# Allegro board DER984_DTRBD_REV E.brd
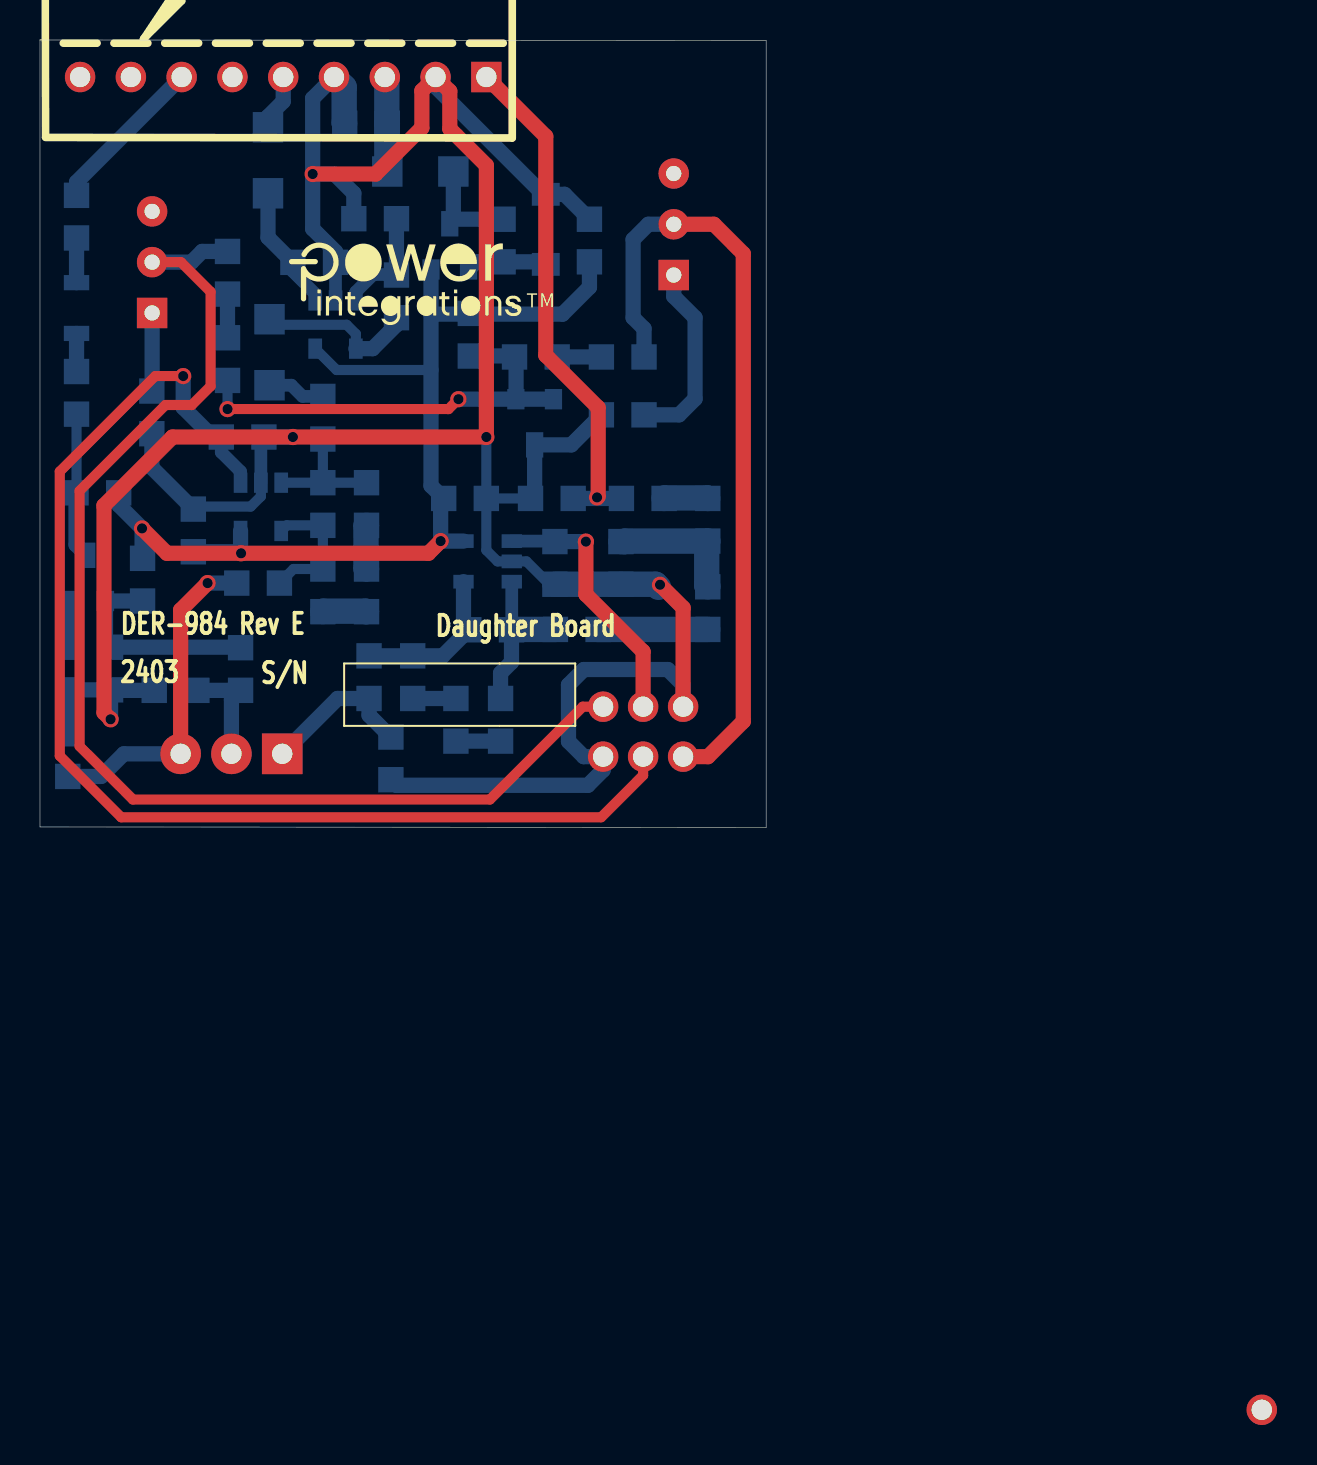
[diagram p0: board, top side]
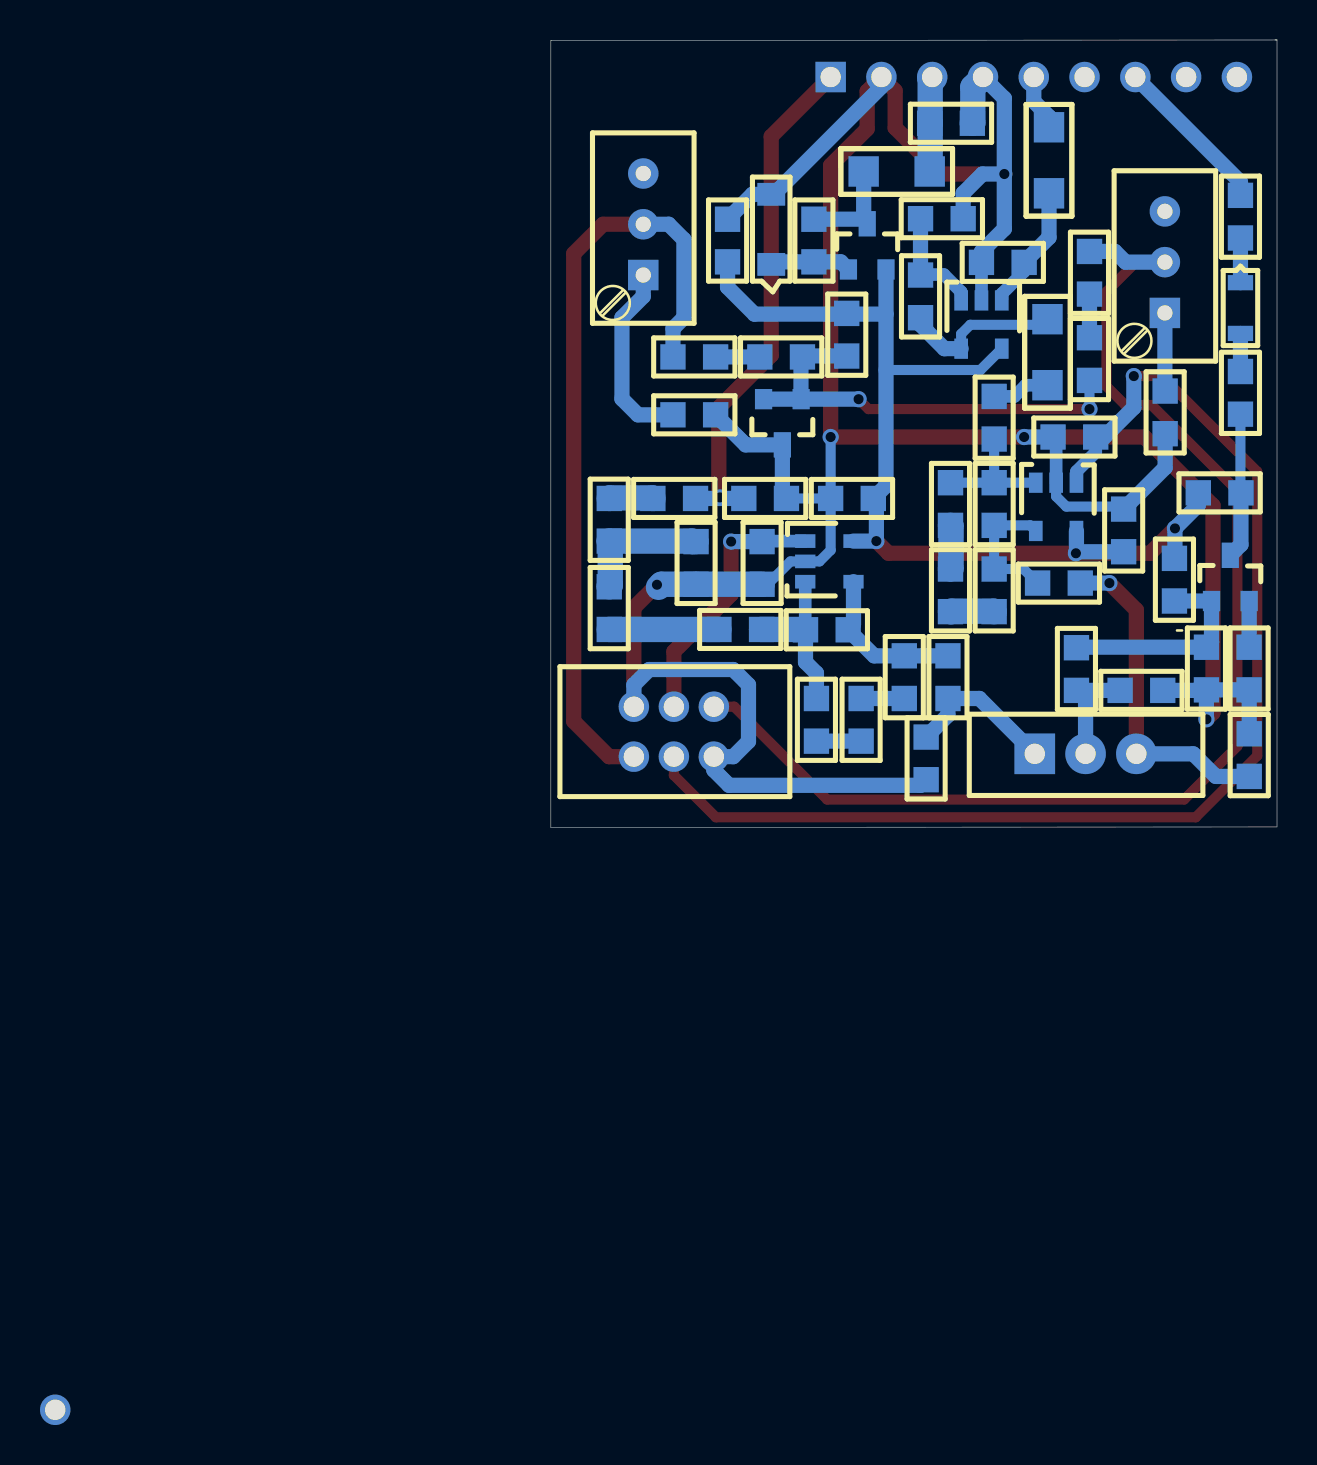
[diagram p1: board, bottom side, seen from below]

Outline 36.32 x 39.4 mm; copper layers: TOP, BOTTOM. Coordinates in mm from the lower left corner of the outline.
Outline path: 0,39.4 0,0.03 36.32,0 36.32,39.37 0,39.4 ; 0,39.4 0.1,39.4 0,39.4

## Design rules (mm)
constraint set DEFAULT: min track width 0.508

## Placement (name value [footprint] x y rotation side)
C1  10 nF  [PISMC0805]  12.65 28.27 0 bottom
C2  100 pf  [PISMC0805]  26.67 16.46 180 bottom
C3  10 uF  [PISMC0805]  17.37 35.23 180 bottom
C7  10 uF  [PISMC0805]  27.48 28.3 90 bottom
C8  10 nF  [PISMC0805]  14.15 10.79 90 bottom
C9  10 nF  [PISMC0805]  18.64 6.45 90 bottom
C10  10 uF  [PISMC0805]  20.19 16.46 0 bottom
C11  10 uF  [PISMC0805]  7.67 13.79 90 bottom
C13  470 nF  [PISMC0805]  14.15 17.25 270 bottom
C14  470 nF  [PISMC0805]  23.58 9.89 180 bottom
D1  BAV16WS-7-F  [PISMSOD323]  1.83 27.25 270 bottom
J9  CON10  [PI_UNSHROUD_10RA]  22.33 37.54 180 top
NOREF  -  []  12.47 29.69 0 top
NOREF#2  -  []  0 0.03 90 top
NOREF#3  -  []  -230.38 -156.18 0 top
NOREF#4  -  []  0 0.03 0 top
NOREF#5  -  []  -152.56 42.83 0 top
Q1  MMBT2222ALT1G  [PISMSOT23123_1]  19.56 27.91 180 bottom
Q2  MMBT2222ALT1G  [PISMSOT23123_1]  1.4 11.33 180 bottom
R1  5.11 k  [PISMR1206]  11.4 31.72 90 bottom
R2  1.00 k  [PISMR0805]  15.7 30.45 0 bottom
R3  0 R  [PISMR1206]  11.48 25.43 270 bottom
R5  0.0  [PISMR0805]  29.08 16.46 0 bottom
R6  2 k  [PISMR0805]  14.15 19.43 90 bottom
R7  9.09 k  [PISMR0805]  17.83 25.5 90 bottom
R8  100 k  [PISMR0805]  33.4 14.33 90 bottom
R9  1.02 k  [PISMR0805]  29.06 12.17 90 bottom
R10  20  [PISMR1206]  17.37 32.82 0 bottom
R11  1 k  [PISMR0805]  23.16 28.3 90 bottom
R13  2 k  [PISMR0805]  33.4 9.91 90 bottom
R17  100 k  [PISMR0805]  11.2 19.53 180 bottom
R18  0.0  [PISMR0805]  27.91 9.91 180 bottom
R19  43 K  [PISMR0805]  16.33 15.11 90 bottom
R20  100 k  [PISMR0805]  25.76 12.17 90 bottom
R21  43 K  [PISMR0805]  23.04 4.32 90 bottom
R22  43 K  [PISMR0805]  16.33 10.79 90 bottom
R23  43 K  [PISMR0805]  20.8 6.45 270 bottom
R25  2.2 k  [PISMR0805]  16.46 6.45 90 bottom
R26  2.2 k  [PISMR0805]  10.03 6.86 90 bottom
R28  14.7 k  [PISMR0805]  5.13 13.46 270 bottom
R29  13.7 k  [PISMR0805]  3.53 9.02 270 bottom
R31  1.00 k  [PISMR0805]  1.8 16.74 0 bottom
R32  300  [PISMR0805]  1.4 9.02 270 bottom
R34  1.00 k  [PISMR0805]  1.83 20.68 90 bottom
R39  0.0  [PISMR0805]  1.83 29.49 90 bottom
R40  1 k  [PISMR0805]  21.52 23.58 90 bottom
R41  316  [PISMR0805]  23.74 23.54 0 bottom
R42  9.1 k  [PISMR0805]  28.08 23.54 0 bottom
R43  5 k  [PIVRESPV36W_MURATA_1]  31.7 27.64 90 bottom
R44  0.0  [PISMR0805]  28.08 20.64 0 bottom
R46  316  [PISMR0805]  9.38 22.36 90 bottom
R47  9.1 k  [PISMR0805]  9.38 26.68 90 bottom
R48  5 k  [PIVRESPV36W_MURATA_1]  5.61 25.74 90 bottom
R49  0.0  [PISMR0805]  5.6 19.7 90 bottom
R50  2.2 k  [PISMR0805]  1.39 4.69 270 bottom
R51  2.2 k  [PISMR0805]  11.98 12.23 180 bottom
R52  2.2 k  [PISMR0805]  17.55 2.39 90 bottom
R53  2.2 k  [PISMR0805]  5.71 6.86 0 bottom
SW1  SPDT SLIDE  [PI_SWITCH_SPDT_SLIDE_PCBM_1]  12.12 3.68 270 bottom
SW2  DPDT SLIDE  [PI_SWITCH_DPDT_SLIDE_EG2209]  28.17 3.54 0 bottom
U1  LM321  [PISMSOT235]  13.77 26.37 0 bottom
U3  LM321  [PISMSOT235]  23.6 14.33 270 bottom
U4  LM321  [PISMSOT235]  10.03 17.25 0 bottom
U6  TL431CDBZR  [PISMSOT23123_1]  25.68 21.42 0 bottom
VR1  MMSZ5234B-TP  [PI_SM_SOD-123_12]  25.3 28.17 90 bottom

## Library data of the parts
C1 C8-C11 = CAP NP: room: 2
C2 C7 C13 C14 = CAP NP
C3 = CAP NP: alternate symbols: (pismc0805_1)
D1 = DIODE
J9 = CON10
Q1 Q2 = NPN_BEC
R1-R3 R6-R11 R13 R17 R19-R23 R25 R26 R28 R29 R31 R32 R34 R40-R42 R46 R47 R50-R53 = R
R5 R18 R39 R44 R49 = R: alternate symbols: (pismr0805_1)
R43 R48 = POT
SW1 = SW SLIDE-SPDT
SW2 = SW SLIDE-DPDT
U1 U4 = LM321_SOT23-5: room: 2
U3 = LM321_SOT23-5
U6 = TL431CDBZR
VR1 = DIODE_ZENER

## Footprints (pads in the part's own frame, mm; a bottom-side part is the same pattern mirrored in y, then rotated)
PI_SM_SOD-123_12
  rect 1.143x1.397 smd: 1(0,0) 2(3.505,0)
PI_SWITCH_DPDT_SLIDE_EG2209
  round 1.524 hole 1.016: 1(0,0) 2(1.999,0) 3(4,0) 4(0,-2.499) 5(1.999,-2.499) 6(4,-2.499)
PI_SWITCH_SPDT_SLIDE_PCBM_1
  rect 2.032x2.032 hole 1.016: 1(0,0)
  round 2.032 hole 1.016: 2(0,2.54) 3(0,5.08)
PI_UNSHROUD_10RA
  rect 1.524x1.524 hole 1.016: 1(0,0)
  round 1.524 hole 1.016: 2(2.54,0) 3(5.08,0) 4(7.62,0) 5(10.16,0) 6(12.7,0) 7(15.24,0) 8(17.78,0) 9(20.32,0) 10(-38.786,66.675)
PISMC0805
  rect 1.27x1.27 smd: 1(0,0) 2(2.134,0)
PISMR0805
  rect 1.27x1.27 smd: 1(0,0) 2(2.134,0)
PISMR1206
  rect 1.524x1.524 smd: 1(0,0) 2(3.302,0)
PISMSOD323
  rect 0.762x1.27 smd: 1(0,0) 2(2.54,0)
PISMSOT235
  rect 0.686x1.016 smd: 1(0,0) 2(1.016,0) 3(2.032,0) 4(2.032,2.413) 5(0,2.413)
PISMSOT23123_1
  rect 0.864x1.016 smd: 1(-1.88,0) 2(0,0)
  rect 0.864x1.27 smd: 3(-0.94,2.286)
PIVRESPV36W_MURATA_1
  rect 1.524x1.524 hole 0.762: 1(0,0)
  round 1.524 hole 0.762: 2(2.54,0) 3(5.08,0)

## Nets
+2.5V_REF: R40.1 R41.1 R46.1 U6.1 U6.2(VREF)
+5V_REF: C7.1 C10.1 C11.1 Q1.2(EMITTER) R28.1 R31.2 R40.2 U1.5 U3.5 U4.5
BPS: C3.1 J9.3 R10.1
CC_COMP: J9.6
CC_FB: J9.7 R39.2
GSA: C1.2 C2.2 C3.2 C7.2 C10.2 C11.2 J9.2 J9.4 R2.1 R9.1 R17.1 R20.1 R29.2 R32.2 R44.1 R49.1 R50.1 R52.1 R53.1 SW2.1 SW2.6 U1.2(V-) U3.2(V-) U4.2(V-) U6.3 VR1.2
HV: C2.1 J9.1 R5.1
ISENSE: J9.5 R1.2
REF_GEN_CC: R42.2 R43.2(WIPER) SW2.3
REF_GEN_CV: R47.2 R48.2(WIPER) SW2.4
REFCC: R17.2 SW2.2 U4.1
REFCV: R20.2 SW2.5 U3.1
N00379: Q1.1 R11.1 VR1.1
N00417: Q1.3 R10.2 R11.2
N01749: C14.1 R18.2 R21.2 U3.3
N01999: C9.2 C14.2 R25.2 U3.4
N02394: R8.1 R9.2 R13.2
N05104: D1.2 R34.2
N05139: D1.1 R39.1
N05314: Q2.1 R26.2 R28.2 R29.1
N05328: Q2.2(EMITTER) R32.1
N05332: Q2.3 R31.1 R34.1
N05564: R26.1 R53.2 SW1.2
N12614042: C8.2 C13.2 R51.1 U4.4
N12614046: C8.1 R22.1
N12615868: C13.1 R6.1 R19.2 U4.3
N12617691: R25.1 R52.2 SW1.1
N12617727: R50.2 R51.2 SW1.3
N12619254: R13.1 R18.1
N12620095: R21.1 R23.2
N12620099: C9.1 R23.1
N12620908: R19.1 R22.2
N12623730: C1.1 R1.1 U1.1
N12624245: R2.2 R7.2 U1.3
N12624261: R3.1 R7.1 U1.4
N12625090: R3.2 R6.2
N12627076: R5.2 R8.2
N12646098: R41.2 R42.1
N12647952: R43.1 R44.2
N12648329: R46.2 R47.1
N12648469: R48.1 R49.2

Pads without a net: J9 8 9 10; R43 3; R48 3

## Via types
v1: diameter 0.813, hole 0.508, TOP to BOTTOM, 14 vias

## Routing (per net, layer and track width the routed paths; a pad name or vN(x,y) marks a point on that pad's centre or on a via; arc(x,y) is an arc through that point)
+2.5V_REF: length 22.3
  TOP w0.508: v1(20.93,21.42) 20.43,20.93 v1(9.38,20.93)
  BOTTOM w0.508: v1(9.38,20.93) R46.1
  BOTTOM w0.762: U6.1 U6.2 ; U6.1 23.8,21.63 23.81,21.64 23.81,23.46 R41.1 23.69,23.59 21.53,23.59 R40.1 ; U6.1 v1(20.93,21.42)
+5V_REF: length 54
  TOP w0.762: v1(5.11,14.96) 6.35,13.72 v1(10.06,13.72) 19.43,13.72 v1(20.04,14.33)
  BOTTOM w0.508: 19.56,22.89 14.83,22.89 U1.5
  BOTTOM w0.762: C7.1 27.48,27.03 26.14,25.68 21.51,25.68 ; 19.56,25.68 19.56,17.09 C10.1 20.04,16.31 v1(20.04,14.33) U3.5 ; 19.56,25.68 21.51,25.68 ; 19.56,25.68 Q1.2 ; 21.51,25.68 21.52,25.69 R40.2 ; R31.2 3.94,16.13 v1(5.11,14.96) 5.11,13.49 R28.1 ; 10.03,13.79 U4.5 ; 10.03,13.79 C11.1 ; 10.03,13.79 10.06,13.77 v1(10.06,13.72)
BPS: length 4.8
  BOTTOM w1.27: J9.3 17.35,37.44 17.35,35.26 C3.1 17.35,35.2 17.35,32.84 R10.1
CC_FB: length 8.1
  BOTTOM w0.762: J9.7 1.83,32.28 R39.2
GSA: length 164.6
  TOP w0.762: SW2.6 32.17,10.99 v1(31.01,12.14) ; v1(13.64,32.69) 16.79,32.69 19.1,35 19.1,36.86 J9.2 20.5,36.83 20.5,34.95 22.33,33.12 v1(22.33,19.53) v1(12.65,19.53) 6.63,19.53 3.2,16.1 3.2,5.74 v1(3.53,5.41)
  BOTTOM w0.508: C11.2 7.8,16.05 10.54,16.05 11.05,16.56 U4.2 ; C10.2 v1(22.33,19.53) ; C10.2 22.33,13.87 22.89,13.31 U3.2 24.33,13.31 25.48,12.17 R20.1 ; C10.2 C2.2
  BOTTOM w0.635: C1.2 U1.2 ; R17.1 11.05,19.38 U4.2
  BOTTOM w0.762: C11.2 5.6,18 R49.1 ; v1(13.64,32.69) 13.64,36.47 J9.4 ; v1(13.64,32.69) 13.64,29.95 14.78,28.8 C1.2 ; v1(13.64,32.69) 14.73,32.69 15.7,31.72 R2.1 ; R53.1 3.56,6.86 R29.2 ; R50.1 1.39,6.88 1.4,6.88 R29.2 ; C7.2 26.24,31.67 VR1.2 25.17,31.67 19.79,37.06 J9.2 ; v1(12.65,19.53) R17.1 ; 30.78,12.17 30.91,12.17 30.94,12.14 v1(31.01,12.14) ; R52.1 17.83,2.11 27.41,2.11 28.17,2.87 SW2.1 27.2,3.54 26.44,4.3 26.44,7.13 27.2,7.9 31.4,7.9 32.17,7.13 SW2.6 ; R44.1 26.58,19.14 U6.3 24.74,16.66 C2.2 ; R29.2 v1(3.53,5.41)
  BOTTOM w1.27: J9.4 15.21,37.03 15.21,35.26 C3.2 ; R20.1 R9.1 30.78,12.17 30.94,12.01
HV: length 25.9
  TOP w0.762: v1(27.86,16.51) 27.92,16.57 27.92,21 25.3,23.62 25.3,34.57 J9.1
  BOTTOM w0.508: 27.91,16.46 v1(27.86,16.51)
  BOTTOM w0.762: R5.1 C2.1
ISENSE: length 2.8
  BOTTOM w0.762: J9.5 12.17,36.32 11.4,35.56 R1.2
REF_GEN_CC: length 39.7
  TOP w0.762: SW2.3 33.41,3.54 35.18,5.31 35.18,28.7 33.71,30.18 R43.2
  BOTTOM w0.762: R43.2 30.43,30.18 29.67,29.41 29.67,25.5 30.21,24.96 R42.2
REF_GEN_CV: length 63
  TOP w0.508: SW2.4 27.15,6.04 22.5,1.4 4.65,1.4 1.98,4.06 1.98,16.84 6.27,21.13 7.59,21.13 8.53,22.07 8.53,26.8 7.05,28.28 R48.2
  BOTTOM w0.762: R47.2 8.11,28.82 7.57,28.28 R48.2
REFCC: length 61.4
  TOP w0.508: v1(7.16,22.58) 5.77,22.58 0.99,17.81 0.99,3.58 4.06,0.51 28.07,0.51 30.17,2.61 SW2.2
  BOTTOM w0.635: U4.1 10.03,17.81 9.07,18.77 R17.2
  BOTTOM w0.762: v1(7.16,22.58) 7.16,21.01 8.64,19.53 R17.2
REFCV: length 13.2
  TOP w0.762: v1(27.3,14.3) 27.3,11.66 30.17,8.8 SW2.5
  BOTTOM w0.635: R20.2 25.65,14.3 25.63,14.33 U3.1
  BOTTOM w0.762: v1(27.3,14.3) R20.2
N00379: length 4.1
  BOTTOM w0.762: Q1.1 21.82,28.3 R11.1 25.17,28.3 VR1.1
N00417: length 5.2
  BOTTOM w0.508: 20.68,30.43 20.62,30.38 20.62,30.33 Q1.3
  BOTTOM w0.762: R10.2 20.68,30.43 20.68,30.43 R11.2
N01749: length 8.3
  BOTTOM w0.508: 23.62,9.91 23.6,9.91 C14.1
  BOTTOM w0.635: 23.62,9.91 23.6,9.93 U3.3
  BOTTOM w0.762: C14.1 23.58,8.27 23.04,7.72 R21.2
  BOTTOM w1.27: 23.62,9.91 R18.2
N01999: length 8
  BOTTOM w0.635: 21.18,10.15 C14.2
  BOTTOM w0.762: R25.2 C9.2 20.15,8.59 C14.2 ; U3.4 21.18,10.15
N02394: length 6.7
  BOTTOM w1.27: R9.2 29.24,14.3 29.26,14.33 R8.1 33.35,14.27 33.35,12.12 33.4,12.06 R13.2
N05104: length 1.9
  BOTTOM w0.762: R34.2 D1.2
N05139: length 2.2
  BOTTOM w0.762: D1.1 R39.1
N05314: length 10.8
  BOTTOM w0.762: R28.2 Q2.1 3.28,9.27 R29.1 9.93,9.02 9.96,8.99 R26.2
N05328: length 2.3
  BOTTOM w0.762: Q2.2 R32.1
N05332: length 7.3
  BOTTOM w0.508: R31.1 1.83,16.76 R34.1
  BOTTOM w0.762: Q2.3 1.8,14.15 R31.1
N05564: length 5.6
  BOTTOM w0.762: 10.03,6.85 R26.1 ; 10.03,6.85 9.58,6.4 SW1.2 ; 10.03,6.85 10.03,6.86 R53.2
N12614042: length 6.8
  BOTTOM w0.508: R51.1 12.68,12.93 C8.2 C13.2 12.34,15.11 U4.4
N12614046: length 2.2
  BOTTOM w1.27: R22.1 16.31,10.79 16.28,10.82 14.17,10.82 C8.1
N12615868: length 6.5
  BOTTOM w0.508: C13.1 R6.1 ; C13.1 R19.2 ; C13.1 U4.3
N12617691: length 7.9
  BOTTOM w0.762: R52.2 16.46,5.61 R25.1 14.88,6.45 SW1.1
N12617727: length 16.7
  TOP w0.762: v1(8.38,12.23) 7.04,10.88 SW1.3
  BOTTOM w0.762: R51.2 v1(8.38,12.23) ; R50.2 3.06,2.55 4.19,3.68 SW1.3
N12619254: length 5.5
  BOTTOM w1.27: R18.1 R13.1
N12620095: length 2.2
  BOTTOM w0.762: R23.2 R21.1
N12620099: length 2.2
  BOTTOM w0.762: R23.1 C9.1
N12620908: length 2.2
  BOTTOM w1.27: R19.1 16.31,15.09 16.31,12.95 R22.2
N12623730: length 6.3
  BOTTOM w0.635: C1.1 12.65,27.81 13.77,26.7 U1.1
  BOTTOM w0.762: C1.1 11.4,29.51 R1.1
N12624245: length 5.6
  BOTTOM w0.508: 17.83,27.66 R7.2
  BOTTOM w0.635: U1.3 15.8,26.79 16.66,27.66 17.83,27.66
  BOTTOM w0.762: R2.2 17.83,27.66
N12624261: length 8.2
  BOTTOM w0.508: R3.1 11.76,25.15 15.34,25.15 15.8,24.69 U1.4
  BOTTOM w0.762: U1.4 16.64,23.95 17.83,25.15 R7.1
N12625090: length 2.9
  BOTTOM w0.635: R3.2 12.57,22.12 13.13,21.56 R6.2
N12627076: length 2.2
  BOTTOM w1.27: R8.2 33.38,16.48 31.24,16.48 R5.2
N12646098: length 2.2
  BOTTOM w0.762: R41.2 R42.1
N12647952: length 9.5
  BOTTOM w0.762: R43.1 31.7,26.57 32.77,25.5 32.77,21.44 31.97,20.64 R44.2
N12648329: length 2.2
  BOTTOM w0.762: R46.2 R47.1
N12648469: length 3.9
  BOTTOM w0.762: R49.2 5.61,21.84 R48.1

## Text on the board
Ref Des/Silkscreen Top: 2403 | DER-984 Rev E | S/N | Daughter Board
User.6: 14.  FAB HOUSE LOGO,DATE CODE TO BE IN SILK SCREEN ONLY.DO NOT USE COPPER. | 13.  MATERIAL FR4 COPPER 2oz THICKNESS 0.062" | NOTES: PLEASE DELETE THESE PINS
User.9: FIGURE | FINISHED_SIZE | 20.0 | 30.0 | 40.0 | DRILL CHART: TOP to BOTTOM | ALL UNITS ARE IN MILS | TOLERANCE_DRILL | +3.0/-3.0 | PLATED | QTY | 14 | 6 | 19 | 39 | TOTAL HOLES:
